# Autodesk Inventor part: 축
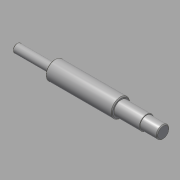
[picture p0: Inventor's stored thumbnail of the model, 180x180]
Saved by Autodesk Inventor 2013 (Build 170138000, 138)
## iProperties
Created: 2016-05
Part Number: 축
Document SubType Name: Modeling
Designer: mduedu
Density: 7.86 g/cm^3
Material: 강철, 연강
Author: mduedu
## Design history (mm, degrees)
sketch "스케치1"
  geometry: L1 (-42, 11)-(-42, 5); L2 (37, 11)-(37, 8.5); L3 (-87, 0)-(87, 0); L4 (-42, 11)-(37, 11); L5 (37, 11)-(37, 8.5); L6 (-42, 11)-(-42, 5); L7 (-42, 5)-(-87, 5); L8 (-87, 5)-(-87, 0); L9 (37, 8.5)-(67, 8.5); L10 (87, 7.5)-(87, 0); L11 (67, 8.5)-(67, 7.5); L12 (67, 7.5)-(87, 7.5); 1 further point
  constraints: 24 end point, 9 perpendicular, 2 midpoint, 1 horizontal
  dimensions: "d0" = 22 diameter of L4 L3; "d1" = 10 diameter of L7 L3; "d2" = 45 distance between parallel lines of L8 L1; "d3" = 50 distance between parallel lines of L10 L2; "d4" = 15 diameter of L12 L3; "d5" = 20 distance between parallel lines of L10 L11; "d29" = 79 distance of L1.start L2.start; "d37" = 17 diameter of L9 L3
revolve "회전1" stored, may be unused: angle "d6" = 90 deg
chamfer "모따기2" distance "d32" = 1; stored, may be unused: second distance "d33" = 2, angle "d34" = 45 deg
node "작업 평면4"
sketch "스케치4"
  geometry: L1 (-5, 2.5)-(5, 2.5); L2 (5, -2.5)-(-5, -2.5); L3 (-10, -6.5)-(-10, 6.5) reference; A1 r 2.5 centre (5, 0) between (5, -2.5) and (5, 2.5); A2 r 2.5 centre (-5, 0) between (-5, 2.5) and (-5, -2.5); 1 further point
  constraints: 4 end point, 4 point on circle, 4 tangent, 2 centre point, 1 horizontal, 1 horizontal alignment, 1 parallel
  dimensions: "d20" = 5 distance between parallel lines of L2 L1; "d21" = 15 dimension on A1 A2; "d35" = 2.5 distance edge to line of A2 L3
extrude "돌출3" cut sketch "스케치4" distance "d23" = 3; taper "d24" = 0 deg
node "작업 평면5"
sketch "스케치5"
  geometry: L1 (22.5, 1.5)-(10, 1.5); L2 (10, -1.5)-(22.5, -1.5); L3 (22.5, 4)-(22.5, -4) reference; A1 r 1.5 centre (10, 0) between (10, 1.5) and (10, -1.5); 3 further points
  constraints: 4 end point, 2 horizontal alignment, 2 point on circle, 2 point on line, 2 tangent, 1 centre point, 1 coincident, 1 horizontal, 1 midpoint
  dimensions: "d25" = 3 distance between parallel lines of L2 L1; "d36" = 14 dimension on A1 L3
extrude "돌출4" cut sketch "스케치5" distance "d27" = 1.8; taper "d28" = 0 deg
node "솔리드1"
